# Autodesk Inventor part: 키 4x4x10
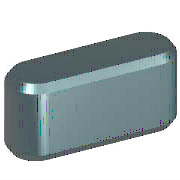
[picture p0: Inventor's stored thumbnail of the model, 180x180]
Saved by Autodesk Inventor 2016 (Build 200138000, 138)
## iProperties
IsCustomPart: 1
Created: 2012-02
Part Number: 키 4x4x10
Material: 강철, 연강
Description: 키 및 해당 키홈
Document SubType Name: Modeling
Standard: KS B 1311
Designer: test
Standards Organization: KS
Language: ko-KR
Size Designation: 4 x 4 x 10
Categories: <MemberInstance><Categories><Category DisplayName="샤프트 부품" InternalName="7f7aeb1f-a693-4053-b835-cee3144e0d98" Mnemonic="SHFT"><Category DisplayName="키" Interna
Density: 1 g/cm^3
Appearance: 노란색
Author: test
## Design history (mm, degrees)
workplane "Work Plane1"
workplane "Work Plane2"
sketch "스케치1"
  geometry: L1 (2, 2)-(8, 2); L2 (8, -2)-(2, -2); L3 (0, 9.4)-(0, -7.4) reference; L4 (-5, 0)-(30, 0) reference; L5 (10, 0)-(10, 7); A1 r 2 centre (2, 0) between (2, 2) and (2, -2); A2 r 2 centre (8, 0) between (8, -2) and (8, 2)
  constraints: 6 end point, 5 point on circle, 4 tangent, 3 point on line, 2 centre point, 1 horizontal, 1 parallel, 1 perpendicular
  dimensions: "d0" = 2 radius of A1 (= 0.5 x PB); "d13" = 2 radius of A2 (= 0.5 x PB); "d14" = 10 distance between parallel lines of L5 L3 (= NLG)
extrude "본체1" new body sketch "스케치1" taper "d3" = 0 deg; stored distance "d4" = 10
workplane "Work Plane3"
body "Solid1"
chamfer "모따기1" distance "d8" = 0.25 (= PHH); stored, may be unused: second distance "d9" = 0.25 (= PHH), angle "d15" = 45 deg
other parameters: "d1" = -2.5 (= -PNT), "d2" = 1.5 (= PH - PNT), "NLG" = 10 [user parameter; used in 3 equation terms], "PB" = 4 [user parameter; used in 2 equation terms], "PNT" = 2.5 [user parameter; used in 2 equation terms], "PH" = 4 [user parameter; used in 1 equation term], "PHH" = 0.25 [user parameter; used in 2 equation terms], "d10" = 0, "d16" = 0, "d17" = 0, "d18" = 0, "WDMAX" = 12 [user parameter], "RR" = 0.08 [user parameter], "PUEB" = 1.8 [user parameter]
